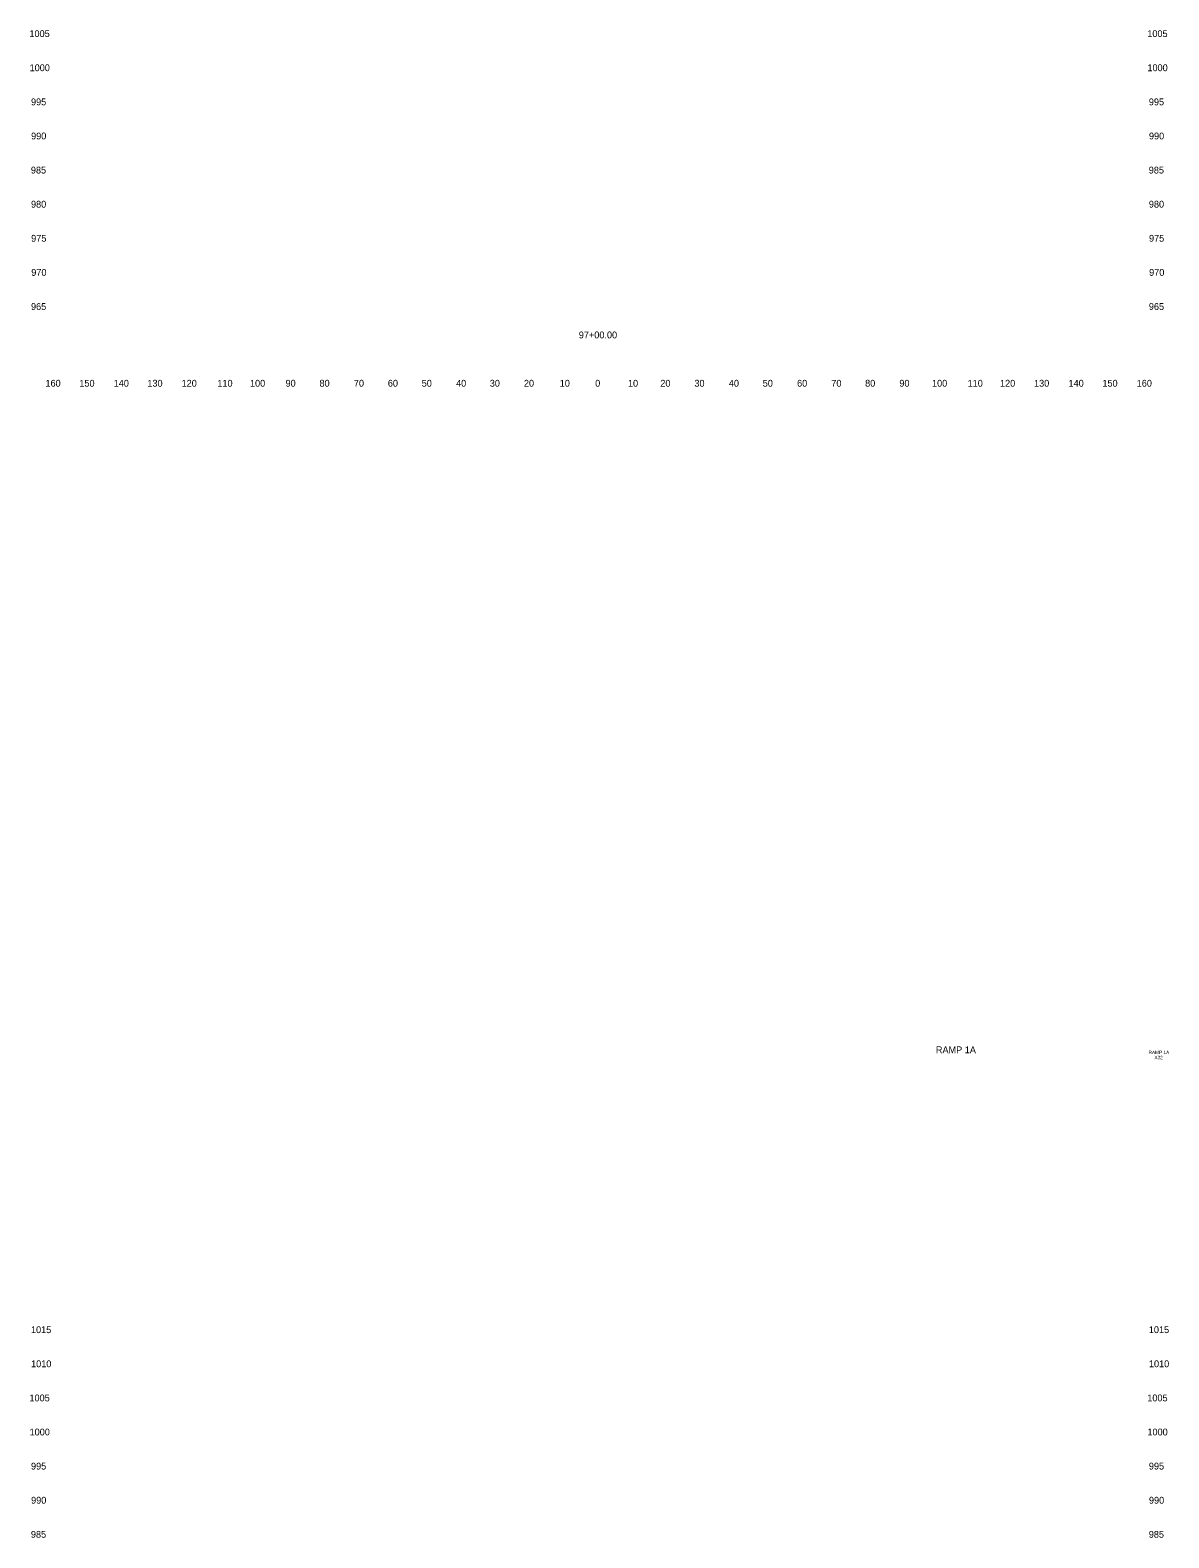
# Model space of a CAD drawing. Extents: x 4994 to 6873, y 4997 to 8804.
# Drawn here: x 6538.6 to 6872.5, y 5460 to 5902 of the extents above; entities that cross this region are included whole.
import ezdxf

# ---------------------------------------------------------------- set-up
doc = ezdxf.new("R2010")
doc.units = 0
for name, color, linetype in [('RD_SHT_ID', 7, 'Continuous'), ('RD_XS_TX_Offset', 7, 'Continuous'), ('RD_XS_TX_Station', 7, 'Continuous')]:
    doc.layers.add(name, color=color, linetype=linetype)

msp = doc.modelspace()

# ---------------------------------------------------------------- texts
at = {"layer": 'RD_SHT_ID'}
for s, height, p in [('RAMP 1A', 2, (6804.21, 5602.06)), ('RAMP 1A', 1, (6866.57, 5601.8)), ('X32', 1, (6868.29, 5600.3))]:
    msp.add_text(s, height=height, dxfattribs=at).set_placement(p)
at = {"layer": 'RD_XS_TX_Offset'}
for s, p in [('1005', (6538.4, 5900)), ('1005', (6866.2, 5900)), ('1000', (6538.44, 5890)), ('1000', (6866.24, 5890)), ('995', (6538.86, 5880)), ('995', (6866.66, 5880)), ('990', (6538.89, 5870)), ('990', (6866.69, 5870)), ('985', (6538.83, 5860)), ('985', (6866.63, 5860)), ('980', (6538.86, 5850)), ('980', (6866.66, 5850)), ('975', (6538.91, 5840)), ('975', (6866.71, 5840)), ('970', (6538.94, 5830)), ('970', (6866.74, 5830)), ('965', (6538.86, 5820)), ('965', (6866.66, 5820)), ('160', (6543.1, 5797.5)), ('150', (6553.04, 5797.5)), ('140', (6563.1, 5797.5)), ('130', (6572.99, 5797.5)), ('120', (6583.01, 5797.5)), ('110', (6593.51, 5797.5)), ('100', (6603.07, 5797.5)), ('90', (6613.5, 5797.5)), ('80', (6623.46, 5797.5)), ('70', (6633.54, 5797.5)), ('60', (6643.5, 5797.5)), ('50', (6653.43, 5797.5)), ('40', (6663.5, 5797.5)), ('30', (6673.39, 5797.5)), ('20', (6683.4, 5797.5)), ('10', (6693.91, 5797.5)), ('0', (6704.3, 5797.5)), ('0', (6704.3, 5797.5)), ('10', (6713.91, 5797.5)), ('20', (6723.4, 5797.5)), ('30', (6733.39, 5797.5)), ('40', (6743.5, 5797.5)), ('50', (6753.43, 5797.5)), ('60', (6763.5, 5797.5)), ('70', (6773.54, 5797.5)), ('80', (6783.46, 5797.5)), ('90', (6793.5, 5797.5)), ('100', (6803.07, 5797.5)), ('110', (6813.51, 5797.5)), ('120', (6823.01, 5797.5)), ('130', (6832.99, 5797.5)), ('140', (6843.1, 5797.5)), ('150', (6853.04, 5797.5)), ('160', (6863.1, 5797.5)), ('1015', (6538.85, 5520)), ('1015', (6866.65, 5520)), ('1010', (6538.88, 5510)), ('1010', (6866.68, 5510)), ('1005', (6538.4, 5500)), ('1005', (6866.2, 5500)), ('1000', (6538.44, 5490)), ('1000', (6866.24, 5490)), ('995', (6538.86, 5480)), ('995', (6866.66, 5480)), ('990', (6538.89, 5470)), ('990', (6866.69, 5470)), ('985', (6538.83, 5460)), ('985', (6866.63, 5460))]:
    msp.add_text(s, height=2, dxfattribs=at).set_placement(p)
at = {"layer": 'RD_XS_TX_Station'}
msp.add_text('97+00.00', height=2, dxfattribs=at).set_placement((6699.5, 5811.67))

doc.saveas('drawing.dxf')
